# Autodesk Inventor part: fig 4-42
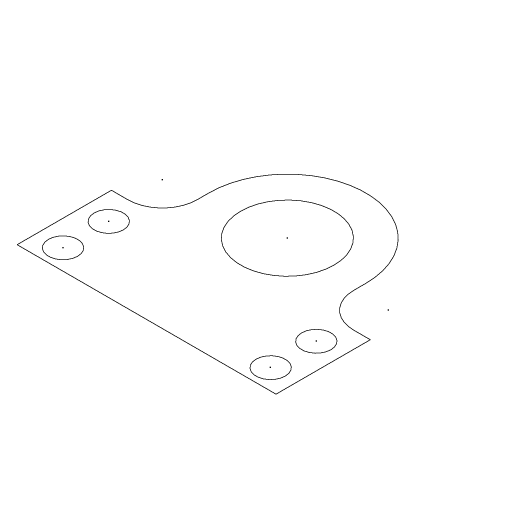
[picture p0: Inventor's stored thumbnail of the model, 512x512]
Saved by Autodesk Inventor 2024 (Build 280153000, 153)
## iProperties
Created: 2004-05
Part Number: fig 4-42
Document SubType Name: Modeling
Designer: CADCIM Technologies
Manufacturer: Standard
Standards Organization: Custom
Density: 1 g/cm^3
Material: Generic
Appearance: Default
Author: CADCIM Technologies
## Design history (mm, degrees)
sketch "Sketch1"
  geometry: L1 (41.331, 50.432)-(41.331, 48.38); L2 (35.331, 42.38)-(32.489, 42.38); L3 (32.489, 42.38)-(32.489, 26.047); L4 (68.481, 50.432)-(68.481, 48.38); L5 (74.481, 42.38)-(77.323, 42.38); L6 (77.323, 42.38)-(77.323, 26.047); L7 (32.489, 26.047)-(77.323, 26.047); C1 r 8.09 at (54.906, 50.432); C2 r 2.534 at (36.931, 29.558); C3 r 2.534 at (36.931, 37.474); C4 r 2.534 at (72.881, 37.474); C5 r 2.534 at (72.881, 29.558); A1 r 13.575 centre (54.906, 50.432) between (68.481, 50.432) and (41.331, 50.432); A2 r 6 centre (35.331, 48.38) between (35.331, 42.38) and (41.331, 48.38); A3 r 6 centre (74.481, 48.38) between (68.481, 48.38) and (74.481, 42.38)
  constraints: 14 end point, 8 centre point, 6 point on circle, 6 tangent, 3 equal length, 2 horizontal, 2 perpendicular, 1 coincident, 1 equal radius, 1 parallel, 1 vertical
